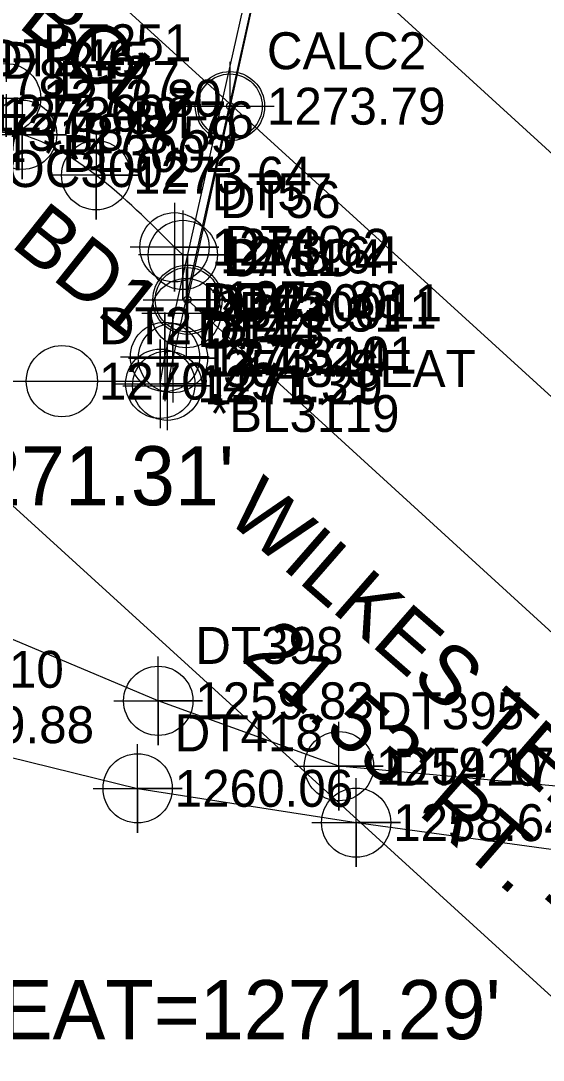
# Model space of a CAD drawing. Extents: x 1390773 to 1392296, y 959928 to 960736.
# Drawn here: x 1391543.3 to 1391578.7, y 960333 to 960403.3 of the extents above; entities that cross this region are included whole.
import ezdxf

# ---------------------------------------------------------------- set-up
doc = ezdxf.new("R2010")
doc.units = 0
for name, color, linetype in [('Cogo Default Point CELL', 7, 'Continuous'), ('COGO Default Point Elevation', 7, 'Continuous'), ('COGO Default Point Number', 7, 'Continuous'), ('Exist Horizontal Alignment', 7, 'Continuous'), ('Exist Hydro Jurisdictional Stream or Body of Water', 7, 'Continuous'), ('Exist Hydro Stream or Body of Water', 7, 'Continuous'), ('Exist Hydro Stream or Body of Water Cogo Elevation', 7, 'Continuous'), ('Exist Hydro Stream or Body of Water Cogo Number', 7, 'Continuous'), ('Exist Hydro Stream or Body of Water Cogo Point CELL', 7, 'Continuous'), ('Exist Other Culture Located Object CELL', 7, 'Continuous'), ('Exist Other Culture Located Object Text', 7, 'Continuous'), ('Exist Right of Way Line', 7, 'Continuous'), ('Exist Roads EOP', 7, 'Continuous'), ('Exist Roads EOP Cogo Comment', 7, 'Continuous'), ('Exist Roads EOP Cogo Elevation', 7, 'Continuous'), ('Exist Roads EOP Cogo Number', 7, 'Continuous'), ('Exist Roads EOP Cogo Point CELL', 7, 'Continuous'), ('Exist Roads EOT Cogo Comment', 7, 'Continuous'), ('Exist Roads EOT Cogo Elevation', 7, 'Continuous'), ('Exist Roads EOT Cogo Number', 7, 'Continuous'), ('Exist Roads EOT Cogo Point CELL', 7, 'Continuous'), ('Exist Structure Major Bridge Seat Top Elevation', 7, 'Continuous'), ('Exist Structure Major Bridge WW', 7, 'Continuous'), ('Exist Structure Major Bridge WW Cogo Comment', 7, 'Continuous'), ('Exist Structure Major Bridge WW Cogo Elevation', 7, 'Continuous'), ('Exist Structure Major Bridge WW Cogo Number', 7, 'Continuous'), ('Exist Structure Major Bridge WW Cogo Point CELL', 7, 'Continuous'), ('Exist Structure Major Deck Tunnel Box Culvert', 7, 'Continuous'), ('Exist Structure Major Deck Tunnel Box Culvert Cogo Comment', 7, 'Continuous'), ('Exist Structure Major Deck Tunnel Box Culvert Cogo Elevation', 7, 'Continuous'), ('Exist Structure Major Deck Tunnel Box Culvert Cogo Number', 7, 'Continuous'), ('Exist Structure Major Deck Tunnel Box Culvert Cogo Point CELL', 7, 'Continuous'), ('Exist Utilities Sanitary Sewer Manhole Cogo Comment', 7, 'Continuous'), ('Exist Utilities Sanitary Sewer Manhole Cogo Elevation', 7, 'Continuous'), ('Exist Utilities Sanitary Sewer Manhole Cogo Number', 7, 'Continuous'), ('Exist Utilities Telephone Pole CELL', 7, 'Continuous'), ('Exist Utilities Telephone Pole Cogo Elevation', 7, 'Continuous'), ('Exist Utilities Telephone Pole Cogo Number', 7, 'Continuous'), ('Exist Utilities Telephone Pole Text', 7, 'Continuous')]:
    doc.layers.add(name, color=color, linetype=linetype)

msp = doc.modelspace()

# ---------------------------------------------------------------- linework, layer by layer
at = {"layer": 'Cogo Default Point CELL'}
for points in [[(1391557.466, 960400.517), (1391557.466, 960397.517)], [(1391554.466, 960397.517), (1391557.466, 960397.517)], [(1391557.466, 960397.517), (1391560.466, 960397.517)], [(1391557.466, 960397.517), (1391557.466, 960394.517)], [(1391554.501, 960386.513), (1391554.501, 960383.513)], [(1391551.501, 960383.513), (1391554.501, 960383.513)], [(1391554.501, 960383.513), (1391557.501, 960383.513)], [(1391554.501, 960383.513), (1391554.501, 960380.513)]]:
    msp.add_lwpolyline(points, dxfattribs=at)
for centre in [(1391557.466, 960397.517), (1391554.501, 960383.513)]:
    msp.add_circle(centre, 2.344, dxfattribs=at)
at = {"layer": 'Exist Horizontal Alignment'}
msp.add_line((1391337.607, 960598.131), (1391677.679, 960288.071), dxfattribs=at)
at = {"layer": 'Exist Hydro Jurisdictional Stream or Body of Water'}
msp.add_lwpolyline([(1391525.646, 960360.725), (1391533.691, 960355.656), (1391551.222, 960351.349), (1391566.005, 960349.028), (1391587.602, 960346.087), (1391590.063, 960325.761), (1391581.908, 960284.337), (1391574.185, 960247.222), (1391569.673, 960235.504)], dxfattribs=at)
at = {"layer": 'Exist Hydro Stream or Body of Water'}
msp.add_lwpolyline([(1391589.108, 960351.82), (1391588.85, 960350.646), (1391564.84, 960352.852), (1391552.616, 960357.272), (1391528.84, 960367.287), (1391524.75, 960364.767)], dxfattribs=at)
at = {"layer": 'Exist Hydro Stream or Body of Water Cogo Point CELL'}
for points in [[(1391549.616, 960357.272), (1391555.616, 960357.272), (1391552.616, 960357.272), (1391552.616, 960354.272), (1391552.616, 960360.272)], [(1391561.84, 960352.852), (1391567.84, 960352.852), (1391564.84, 960352.852), (1391564.84, 960349.852), (1391564.84, 960355.852)], [(1391548.222, 960351.349), (1391554.222, 960351.349), (1391551.222, 960351.349), (1391551.222, 960348.349), (1391551.222, 960354.349)], [(1391563.005, 960349.028), (1391569.005, 960349.028), (1391566.005, 960349.028), (1391566.005, 960346.028), (1391566.005, 960352.028)]]:
    msp.add_lwpolyline(points, dxfattribs=at)
for centre in [(1391552.616, 960357.272), (1391564.84, 960352.852), (1391551.222, 960351.349), (1391566.005, 960349.028)]:
    msp.add_circle(centre, 2.344, dxfattribs=at)
at = {"layer": 'Exist Other Culture Located Object CELL'}
for centre, radius in [((1391557.466, 960397.517), 2.18), ((1391557.466, 960397.517), 0.24), ((1391554.593, 960384.418), 2.18), ((1391554.593, 960384.418), 0.24)]:
    msp.add_circle(centre, radius, dxfattribs=at)
at = {"layer": 'Exist Right of Way Line'}
msp.add_line((1391525.055, 960386.628), (1391657.467, 960265.902), dxfattribs=at)
at = {"layer": 'Exist Roads EOP'}
msp.add_line((1391554.278, 960387.449), (1391553.715, 960387.967), dxfattribs=at)
msp.add_spline([(1391553.715, 960387.967), (1391548.413, 960392.843), (1391543.408, 960395.581), (1391535.709, 960395.746), (1391529.074, 960394.424), (1391522.155, 960390.501), (1391514.618, 960381.223), (1391511.262, 960369.19), (1391511.324, 960340.675), (1391514.177, 960312.818)], degree=3, dxfattribs=at)
at = {"layer": 'Exist Roads EOP Cogo Point CELL'}
for points in [[(1391543.408, 960398.581), (1391543.408, 960392.581), (1391543.408, 960395.581), (1391546.408, 960395.581), (1391540.408, 960395.581)], [(1391548.413, 960395.843), (1391548.413, 960389.843), (1391548.413, 960392.843), (1391551.413, 960392.843), (1391545.413, 960392.843)], [(1391553.715, 960390.967), (1391553.715, 960384.967), (1391553.715, 960387.967), (1391556.715, 960387.967), (1391550.715, 960387.967)], [(1391554.278, 960390.449), (1391554.278, 960384.449), (1391554.278, 960387.449), (1391557.278, 960387.449), (1391551.278, 960387.449)]]:
    msp.add_lwpolyline(points, dxfattribs=at)
for centre in [(1391543.408, 960395.581), (1391548.413, 960392.843), (1391553.715, 960387.967), (1391554.278, 960387.449)]:
    msp.add_circle(centre, 2.344, dxfattribs=at)
at = {"layer": 'Exist Roads EOT Cogo Point CELL'}
msp.add_lwpolyline([(1391542.319, 960401.059), (1391542.319, 960395.059), (1391542.319, 960398.059), (1391539.319, 960398.059), (1391545.319, 960398.059)], dxfattribs=at)
msp.add_circle((1391542.319, 960398.059), 2.344, dxfattribs=at)
at = {"layer": 'Exist Structure Major Bridge WW'}
msp.add_lwpolyline([(1391553.61, 960380.468), (1391553.224, 960378.599), (1391552.754, 960378.73), (1391553.071, 960380.55), (1391560.801, 960415.01), (1391561.247, 960416.559), (1391561.672, 960416.522), (1391561.258, 960414.84), (1391553.61, 960380.468)], dxfattribs=at)
at = {"layer": 'Exist Structure Major Bridge WW Cogo Point CELL'}
for points in [[(1391550.071, 960380.55), (1391556.071, 960380.55), (1391553.071, 960380.55), (1391553.071, 960383.55), (1391553.071, 960377.55)], [(1391550.61, 960380.468), (1391556.61, 960380.468), (1391553.61, 960380.468), (1391553.61, 960383.468), (1391553.61, 960377.468)], [(1391549.754, 960378.73), (1391555.754, 960378.73), (1391552.754, 960378.73), (1391552.754, 960381.73), (1391552.754, 960375.73)], [(1391550.224, 960378.599), (1391556.224, 960378.599), (1391553.224, 960378.599), (1391553.224, 960381.599), (1391553.224, 960375.599)]]:
    msp.add_lwpolyline(points, dxfattribs=at)
for centre in [(1391553.071, 960380.55), (1391553.61, 960380.468), (1391552.754, 960378.73), (1391553.224, 960378.599)]:
    msp.add_circle(centre, 2.344, dxfattribs=at)
at = {"layer": 'Exist Structure Major Deck Tunnel Box Culvert'}
msp.add_lwpolyline([(1391654.21, 960293.41), (1391660.197, 960320.407), (1391560.527, 960411.423), (1391554.593, 960384.418), (1391654.21, 960293.41)], dxfattribs=at)
at = {"layer": 'Exist Structure Major Deck Tunnel Box Culvert Cogo Point CELL'}
msp.add_lwpolyline([(1391551.593, 960384.418), (1391557.593, 960384.418), (1391554.593, 960384.418), (1391554.593, 960387.418), (1391554.593, 960381.418)], dxfattribs=at)
msp.add_circle((1391554.593, 960384.418), 2.344, dxfattribs=at)
at = {"layer": 'Exist Utilities Telephone Pole CELL'}
for p, q in [((1391540.422, 960378.907), (1391551.759, 960378.907)), ((1391546.097, 960378.907), (1391546.097, 960378.907))]:
    msp.add_line(p, q, dxfattribs=at)
msp.add_circle((1391546.097, 960378.907), 2.407, dxfattribs=at)

# ---------------------------------------------------------------- texts
at = {"layer": 'COGO Default Point Elevation'}
for s, p in [('1273.79', (1391559.966, 960396.267)), ('1273.69', (1391541.991, 960395.624)), ('1271.31', (1391557.001, 960382.263))]:
    msp.add_text(s, height=2.5, dxfattribs=at).set_placement(p)
at = {"layer": 'COGO Default Point Number'}
for s, p in [('CALC2', (1391559.966, 960400.017)), ('DT245', (1391541.991, 960399.374)), ('CALC4', (1391557.001, 960386.013))]:
    msp.add_text(s, height=2.5, dxfattribs=at).set_placement(p)
at = {"layer": 'Exist Hydro Stream or Body of Water Cogo Elevation'}
for s, p in [('1259.83', (1391555.116, 960356.022)), ('1259.88', (1391536.191, 960354.406)), ('1259.17', (1391567.34, 960351.602)), ('1260.06', (1391553.722, 960350.099)), ('1258.64', (1391568.505, 960347.778))]:
    msp.add_text(s, height=2.5, dxfattribs=at).set_placement(p)
at = {"layer": 'Exist Hydro Stream or Body of Water Cogo Number'}
for s, p in [('DT398', (1391555.116, 960359.772)), ('DT410', (1391536.191, 960358.156)), ('DT395', (1391567.34, 960355.352)), ('DT418', (1391553.722, 960353.849)), ('DT420', (1391568.505, 960351.528))]:
    msp.add_text(s, height=2.5, dxfattribs=at).set_placement(p)
at = {"layer": 'Exist Other Culture Located Object Text'}
for s, p in [('BCL1', (1391543.032, 960402.938)), ('BD1', (1391542.533, 960388.092))]:
    msp.add_text(s, height=4, rotation=321.50919, dxfattribs=at).set_placement(p)
at = {"layer": 'Exist Roads EOP Cogo Comment'}
for s, p in [('*OC30011', (1391556.215, 960382.967)), ('*BL30011', (1391556.778, 960382.449))]:
    msp.add_text(s, height=2.5, dxfattribs=at).set_placement(p)
at = {"layer": 'Exist Roads EOP Cogo Elevation'}
for s, p in [('1273.48', (1391538.209, 960394.496)), ('1273.59', (1391545.908, 960394.331)), ('1273.34', (1391531.574, 960393.174)), ('1273.64', (1391550.913, 960391.593)), ('1273.62', (1391556.215, 960386.717)), ('1273.64', (1391556.778, 960386.199))]:
    msp.add_text(s, height=2.5, dxfattribs=at).set_placement(p)
at = {"layer": 'Exist Roads EOP Cogo Number'}
for s, p in [('DT78', (1391538.209, 960398.246)), ('DT77', (1391545.908, 960398.081)), ('DT76', (1391550.913, 960395.343)), ('DT57', (1391556.215, 960390.467)), ('DT56', (1391556.778, 960389.949))]:
    msp.add_text(s, height=2.5, dxfattribs=at).set_placement(p)
at = {"layer": 'Exist Roads EOT Cogo Comment'}
for s, p in [('*BL3002', (1391544.819, 960393.059)), ('*OC3002', (1391541.033, 960392.042))]:
    msp.add_text(s, height=2.5, dxfattribs=at).set_placement(p)
at = {"layer": 'Exist Roads EOT Cogo Elevation'}
for s, p in [('1273.80', (1391544.819, 960396.809)), ('1273.69', (1391541.033, 960395.792))]:
    msp.add_text(s, height=2.5, dxfattribs=at).set_placement(p)
at = {"layer": 'Exist Roads EOT Cogo Number'}
for s, p in [('DT251', (1391544.819, 960400.559)), ('DT246', (1391541.033, 960399.542))]:
    msp.add_text(s, height=2.5, dxfattribs=at).set_placement(p)
at = {"layer": 'Exist Structure Major Bridge Seat Top Elevation'}
for s, p in [("SEAT=1271.31'", (1391520.286, 960370.505)), ("SEAT=1271.29'", (1391538.334, 960334.373))]:
    msp.add_text(s, height=4, dxfattribs=at).set_placement(p)
at = {"layer": 'Exist Structure Major Bridge WW Cogo Comment'}
msp.add_text('*BL3119', height=2.5, dxfattribs=at).set_placement((1391556.11, 960375.468))
at = {"layer": 'Exist Structure Major Bridge WW Cogo Elevation'}
for s, p in [('1273.24', (1391555.571, 960379.3)), ('1273.24', (1391556.11, 960379.218)), ('1271.31', (1391555.254, 960377.48)), ('1271.29', (1391555.724, 960377.349))]:
    msp.add_text(s, height=2.5, dxfattribs=at).set_placement(p)
at = {"layer": 'Exist Structure Major Bridge WW Cogo Number'}
for s, p in [('DT45', (1391555.571, 960383.05)), ('DT42', (1391556.11, 960382.968)), ('DT44', (1391555.254, 960381.23)), ('DT43', (1391555.724, 960381.099))]:
    msp.add_text(s, height=2.5, dxfattribs=at).set_placement(p)
at = {"layer": 'Exist Structure Major Deck Tunnel Box Culvert Cogo Comment'}
msp.add_text('*CL3101', height=2.5, dxfattribs=at).set_placement((1391557.093, 960379.418))
at = {"layer": 'Exist Structure Major Deck Tunnel Box Culvert Cogo Elevation'}
msp.add_text('1273.38', height=2.5, dxfattribs=at).set_placement((1391557.093, 960383.168))
at = {"layer": 'Exist Structure Major Deck Tunnel Box Culvert Cogo Number'}
msp.add_text('DT40', height=2.5, dxfattribs=at).set_placement((1391557.093, 960386.918))
at = {"layer": 'Exist Utilities Sanitary Sewer Manhole Cogo Comment'}
msp.add_text('3543 SEAT', height=2.5, dxfattribs=at).set_placement((1391557.001, 960378.513))
at = {"layer": 'Exist Utilities Sanitary Sewer Manhole Cogo Elevation'}
msp.add_text('1271.31', height=2.5, dxfattribs=at).set_placement((1391557.001, 960382.263))
at = {"layer": 'Exist Utilities Sanitary Sewer Manhole Cogo Number'}
msp.add_text('DT51', height=2.5, dxfattribs=at).set_placement((1391557.001, 960386.013))
at = {"layer": 'Exist Utilities Telephone Pole Cogo Elevation'}
msp.add_text('1270.49', height=2.5, dxfattribs=at).set_placement((1391548.597, 960377.657))
at = {"layer": 'Exist Utilities Telephone Pole Cogo Number'}
msp.add_text('DT278', height=2.5, dxfattribs=at).set_placement((1391548.597, 960381.407))
at = {"layer": 'Exist Utilities Telephone Pole Text'}
for s, p in [('WILKES TELEPHONE', (1391557.074, 960369.651)), ("21.53' RT. -EL-", (1391558.133, 960360.105))]:
    msp.add_text(s, height=4, rotation=318.9216, dxfattribs=at).set_placement(p)

doc.saveas('drawing.dxf')
